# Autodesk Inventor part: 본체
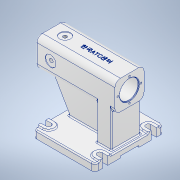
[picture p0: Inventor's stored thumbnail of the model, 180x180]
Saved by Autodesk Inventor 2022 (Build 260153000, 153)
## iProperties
Created: 2024-07
Part Number: 본체
Material: 알루미늄 6061
Document SubType Name: Modeling
Designer: PC-01
Mass: 5666.01 g
Surface Area: 2208.03 cm^2
Volume: 2098.52 cm^3
Density: 2.7 g/cm^3
Appearance: 알루미늄 - 평지
Author: PC-01
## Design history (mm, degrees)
sketch "스케치1"
  geometry: L1 (85, 95)-(-85, 95); L2 (-85, 95)-(-85, -95); L3 (-85, -95)-(85, -95); L4 (85, -95)-(85, 95); L5 (85, 95)-(-85, -95); L6 (-85, 95)-(85, -95); 1 further point
  constraints: 12 end point, 2 midpoint, 2 parallel, 1 horizontal, 1 perpendicular
  dimensions: "d0" = 170 distance of L3.end L2.end; "d1" = 190 distance of L2.end L1.end
extrude "돌출1" new body sketch "스케치1" distance "d2" = 20; taper "d3" = 0 deg
sketch "스케치2"
  geometry: L1 (55, 110)-(135, 110); L2 (135, 110)-(135, 190); L3 (135, 190)-(55, 190); L4 (55, 190)-(55, 110); L5 (55, 110)-(135, 190); L6 (135, 110)-(55, 190); L7 (0, 0)-(190, 0) reference; 4 further points
  constraints: 12 end point, 4 midpoint, 2 parallel, 1 horizontal, 1 perpendicular, 1 vertical alignment
  dimensions: "d4" = 80 distance of L3.end L2.end; "d5" = 80 distance of L2.end L1.end; "d6" = 150 distance from line of L7 point (95, 150)
extrude "돌출2" join sketch "스케치2" distance "d7" = 217; taper "d8" = 0 deg
fillet "모깎기1" dims "d9" = 15
fillet "모깎기2" dims "d10" = 10
sketch "스케치3"
  geometry: L1 (-53.491, 0)-(75, 0); L2 (75, 0)-(75, 110); L3 (75, 110)-(-117, 110); L4 (-117, 110)-(-53.491, 0); L5 (75, 20)-(-75, 20) reference; L6 (85, 125)-(85, 110) reference; L7 (-132, 110)-(-132, 125) reference; 4 further points
  constraints: 8 end point, 2 horizontal alignment, 2 perpendicular, 1 horizontal, 1 midpoint
  dimensions: "d12" = 120 deg angle of L5 L4; "d13" = 10 distance between parallel lines of L6 L2; "d14" = 15 distance from line of L7 L3.end
extrude "돌출3" join sketch "스케치3" stored distance "d15" = 30; taper "d16" = 0 deg
sketch "스케치4"
  geometry: L1 (35, -40)-(75, -40); L2 (75, -40)-(75, 40); L3 (75, 40)-(35, 40); L4 (35, 40)-(35, -40); L5 (35, -40)-(75, 40); L6 (75, -40)-(35, 40); L7 (85, -85)-(85, 85) reference; 3 further points
  constraints: 12 end point, 3 midpoint, 2 parallel, 1 horizontal, 1 horizontal alignment, 1 perpendicular
  dimensions: "d17" = 10 distance between parallel lines of L2 L7; "d18" = 80 distance between parallel lines of L1 L3; "d19" = 40 distance between parallel lines of L4 L2
extrude "돌출4" join sketch "스케치4" distance "d20" = 150; taper "d21" = 0 deg
sketch "스케치5"
  geometry: L1 (10, 0)-(180, 0) reference; C1 r 20.5 at (95, 150); 2 further points
  constraints: 1 centre point, 1 midpoint, 1 vertical alignment
  dimensions: "d22" = 41 diameter of C1; "d23" = 150 distance from line of L1 C1.centre
extrude "돌출5" cut sketch "스케치5" extent not by distance; stored distance "d24" = 0; taper "d25" = 0 deg
sketch "스케치6"
  geometry: C1 r 26 at (95, 150); C2 r 20.5 at (95, 150) reference; 1 further point
  constraints: 1 centre point, 1 concentric
  dimensions: "d26" = 52 diameter of C1
extrude "돌출6" cut sketch "스케치6" distance "d27" = 212; taper "d28" = 0 deg
sketch "스케치7"
  geometry: L1 (55, 67)-(127.926, 67); L2 (70, 82)-(112.926, 82); L3 (112.926, 52)-(70, 52); L4 (55, -67)-(127.926, -67); L5 (70, -52)-(112.926, -52); L6 (112.926, -82)-(70, -82); L7 (-55, -67)-(-127.303, -67); L8 (-70, -52)-(-112.303, -52); L9 (-112.303, -82)-(-70, -82); L10 (-55, 67)-(-127.303, 67); L11 (-70, 82)-(-112.303, 82); L12 (-112.303, 52)-(-70, 52); L13 (-85, 85)-(-85, -85) reference; L14 (85, -85)-(85, 85) reference; L15 (112.926, 67)-(112.926, -67); L16 (-112.303, 67)-(-112.303, -67); A1 r 15 centre (70, 67) between (70, 82) and (70, 52); A2 r 15 centre (112.926, 67) between (112.926, 52) and (112.926, 82); A3 r 15 centre (70, -67) between (70, -52) and (70, -82); A4 r 15 centre (112.926, -67) between (112.926, -82) and (112.926, -52); A5 r 15 centre (-70, -67) between (-70, -82) and (-70, -52); A6 r 15 centre (-112.303, -67) between (-112.303, -52) and (-112.303, -82); A7 r 15 centre (-70, 67) between (-70, 52) and (-70, 82); A8 r 15 centre (-112.303, 67) between (-112.303, 82) and (-112.303, 52); 15 further points
  constraints: 36 end point, 24 point on circle, 16 tangent, 8 centre point, 8 point on line, 7 parallel, 6 midpoint, 2 horizontal, 2 horizontal alignment, 2 perpendicular, 1 collinear
  dimensions: "d29" = 15 distance from line of L13 A7.centre; "d30" = 15 distance from line of A1.centre L14; "d31" = 15 distance from line of L14 A3.centre; "d33" = 15 distance from line of L13 A5.centre; "d34" = 30 distance between parallel lines of L9 L8; "d35" = 30 distance between parallel lines of L6 L5; "d36" = 30 distance between parallel lines of L11 L12; "d37" = 30 distance between parallel lines of L3 L2; "d38" = 134 distance between parallel lines of L4 L1
extrude "돌출7" join sketch "스케치7" distance "d39" = 3; taper "d40" = 0 deg
sketch "스케치8"
  geometry: L1 (63, 67)-(103.003, 67); L2 (70, 74)-(96.003, 74); L3 (96.003, 60)-(70, 60); L4 (98.674, -67)-(63, -67); L5 (91.674, -74)-(70, -74); L6 (70, -60)-(91.674, -60); L7 (-116.603, -67)-(-63, -67); L8 (-123.603, -60)-(-70, -60); L9 (-70, -74)-(-123.603, -74); L10 (-133.385, 67)-(-63, 67); L11 (-126.385, 74)-(-70, 74); L12 (-70, 60)-(-126.385, 60); L13 (-116.603, 67)-(-116.603, -67); L14 (80.837, 67)-(80.837, -67); L15 (-85, 82)-(-85, 52) reference; L16 (85, 52)-(85, 82) reference; L17 (85, -82)-(85, -52) reference; L18 (-85, -52)-(-85, -82) reference; A1 r 7 centre (70, 67) between (70, 74) and (70, 60); A2 r 7 centre (96.003, 67) between (96.003, 60) and (96.003, 74); A3 r 7 centre (91.674, -67) between (91.674, -74) and (91.674, -60); A4 r 7 centre (70, -67) between (70, -60) and (70, -74); A5 r 7 centre (-123.603, -67) between (-123.603, -60) and (-123.603, -74); A6 r 7 centre (-70, -67) between (-70, -74) and (-70, -60); A7 r 7 centre (-126.385, 67) between (-126.385, 74) and (-126.385, 60); A8 r 7 centre (-70, 67) between (-70, 60) and (-70, 74); 6 further points
  constraints: 36 end point, 24 point on circle, 16 tangent, 12 point on line, 8 centre point, 6 midpoint, 6 parallel, 2 horizontal alignment, 2 perpendicular, 1 collinear, 1 horizontal
  dimensions: "d41" = 134 distance between parallel lines of L4 L1; "d42" = 15 distance from line of L15 A8.centre; "d43" = 15 distance from line of A1.centre L16; "d44" = 15 distance from line of L17 A4.centre; "d45" = 15 distance from line of L18 A6.centre; "d46" = 14 distance between parallel lines of L9 L8; "d47" = 14 distance between parallel lines of L11 L12; "d48" = 14 distance from line of L3 L2.end; "d49" = 14 distance between parallel lines of L5 L6
extrude "돌출8" cut sketch "스케치8" extent not by distance; stored distance "d50" = 0; taper "d51" = 0 deg
sketch "스케치9"
  geometry: L1 (0, 50)-(0, 0) reference; 3 further points
  constraints: 1 horizontal alignment, 1 midpoint
  dimensions: "d52" = 177 distance from line of L1 point (-177, 25)
hole "구멍1" sketch "스케치9" at (-177, 25) diameter "d53" = 10.106; stored, may be unused: countersink angle "d57" = 90 deg, drill point angle "d59" = 118 deg; dims "d54" = 30, "d55" = 30, "d56" = 2, "d58" = 32.3
sketch "스케치10"
  geometry: L1 (-217, 0)-(-217, 50) reference; L2 (0, 50)-(0, 0) reference; 3 further points
  constraints: 1 horizontal alignment, 1 midpoint
  dimensions: "d60" = 177 distance from line of L2 point (-177, 25)
hole "구멍2" sketch "스케치10" at (-177, 25) diameter "d61" = 10.106; stored, may be unused: countersink angle "d65" = 90 deg, drill point angle "d67" = 118 deg; dims "d62" = 30, "d63" = 30, "d64" = 2, "d66" = 8
sketch "스케치11"
  geometry: L1 (0, 0)-(0, 50) reference; 3 further points
  constraints: 1 horizontal alignment, 1 midpoint
  dimensions: "d68" = 177 distance from line of L1 point (177, 25)
hole "구멍3" sketch "스케치11" at (177, 25) diameter "d69" = 10.106; stored, may be unused: countersink angle "d73" = 90 deg, drill point angle "d75" = 118 deg; dims "d70" = 30, "d71" = 30, "d72" = 2, "d74" = 8
sketch "스케치12" dims "d76" = 64
  geometry: C1 r 26 at (95, 150) reference; 3 further points
  constraints: 2 vertical alignment, 3 other
hole "구멍4" sketch "스케치12" at (95, 182) diameter "d77" = 4.917; stored, may be unused: countersink angle "d81" = 90 deg, drill point angle "d83" = 118 deg; dims "d78" = 12, "d79" = 30, "d80" = 2, "d82" = 14
chamfer "모따기1" distance "d87" = 2; stored, may be unused: second distance "d88" = 2, angle "d89" = 30 deg
fillet "모깎기3" dims "d90" = 2
fillet "모깎기4" dims "d91" = 1
fillet "모깎기5" dims "d92" = 3
fillet "모깎기6" dims "d93" = 3
fillet "모깎기7" dims "d94" = 3
sketch "스케치13"
  geometry: L1 (35, 5)-(85, 5); L2 (85, 5)-(85, -8.714); L3 (85, -8.714)-(35, -8.714); L4 (35, -8.714)-(35, 5); L5 (0, 0)-(120, 0) reference; 3 further points
  constraints: 8 end point, 2 midpoint, 2 parallel, 1 horizontal, 1 perpendicular, 1 vertical alignment
  dimensions: "d95" = 50 distance between parallel lines of L4 L2; "d96" = 5 distance between parallel lines of L5 L1
extrude "돌출9" cut sketch "스케치13" extent not by distance; stored distance "d97" = 0; taper "d98" = 0 deg
chamfer "모따기2" distance "d99" = 1; stored, may be unused: second distance "d100" = 2, angle "d101" = 30 deg
fillet "모깎기8" dims "d102" = 3
sketch "스케치14"
  geometry: L1 (0, 50)-(0, 0) reference; 2 further points
  constraints: 1 horizontal alignment, 1 other
  dimensions: "d103" = 90 distance from line of L1 point (-90, 25)
feature "엠보싱1" sketch "스케치14" dims "d0" = 170, "d1" = 190, "d9" = 15, "d104" = 0.5, "d105" = 0
node "솔리드1"
pattern_circular "원형 패턴1" dims angle "d85" = 360 deg
feature "A9D066F2-1C7D-4E18-AEED-F7BC21143FA4" dims "d77" = 4.917, "d78" = 12, "d79" = 30, "d80" = 2, "d81" = 90 deg, "d82" = 14, "d83" = 118 deg
